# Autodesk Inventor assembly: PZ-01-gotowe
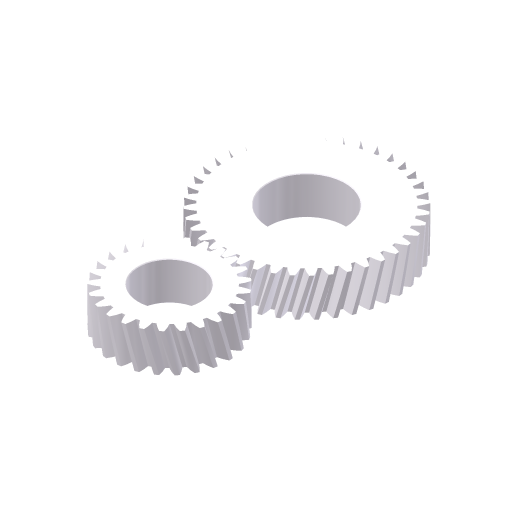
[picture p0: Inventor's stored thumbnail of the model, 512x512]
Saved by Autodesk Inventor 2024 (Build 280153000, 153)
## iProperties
Company: ATC
ClientObjectVersion: 1
Created: 2023-03
Part Number: PZ-01-gotowe
Document SubType Name: Assembly
Designer: Andrzej Jaskulski
Categories: <?xml version="1.0" encoding="UTF-16"?> <MemberInstance><Categories><FamilyTemplate/><ParamToTemplateMap><ParamToTemplate><ParamToTemplate CategoryParameter="//
Stock Number: PZ-01-gotowe
Checked By: A.J.
Engr Approved By: Andrzej Jaskulski
Mfg Approved By: Andrzej Jaskulski
Authority: A.J.
Title: A.J.: Kurs R2024-MEP
Author: Andrzej Jaskulski
Revision Number: 1/24
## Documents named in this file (3)
- C:\Users\AndJas\Documents\R2024-MEP\Obszar roboczy\PZ\GOTOWE\PZ-01-gotowe.iam
- C:\Users\AndJas\Documents\R2024-MEP\Obszar roboczy\PZ\GOTOWE\K-01-gotowe.ipt
- C:\Users\AndJas\Documents\R2024-MEP\Obszar roboczy\PZ\GOTOWE\K-02-gotowe.ipt
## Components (2 placed, 2 different names)
1. K-01:1 — Obrót:1
2. K-02:1 — Obrót:1
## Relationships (1: RelateRotation 1)
- Obrót:1 [RelateRotation]: K-01:1 ↔ K-02:1
